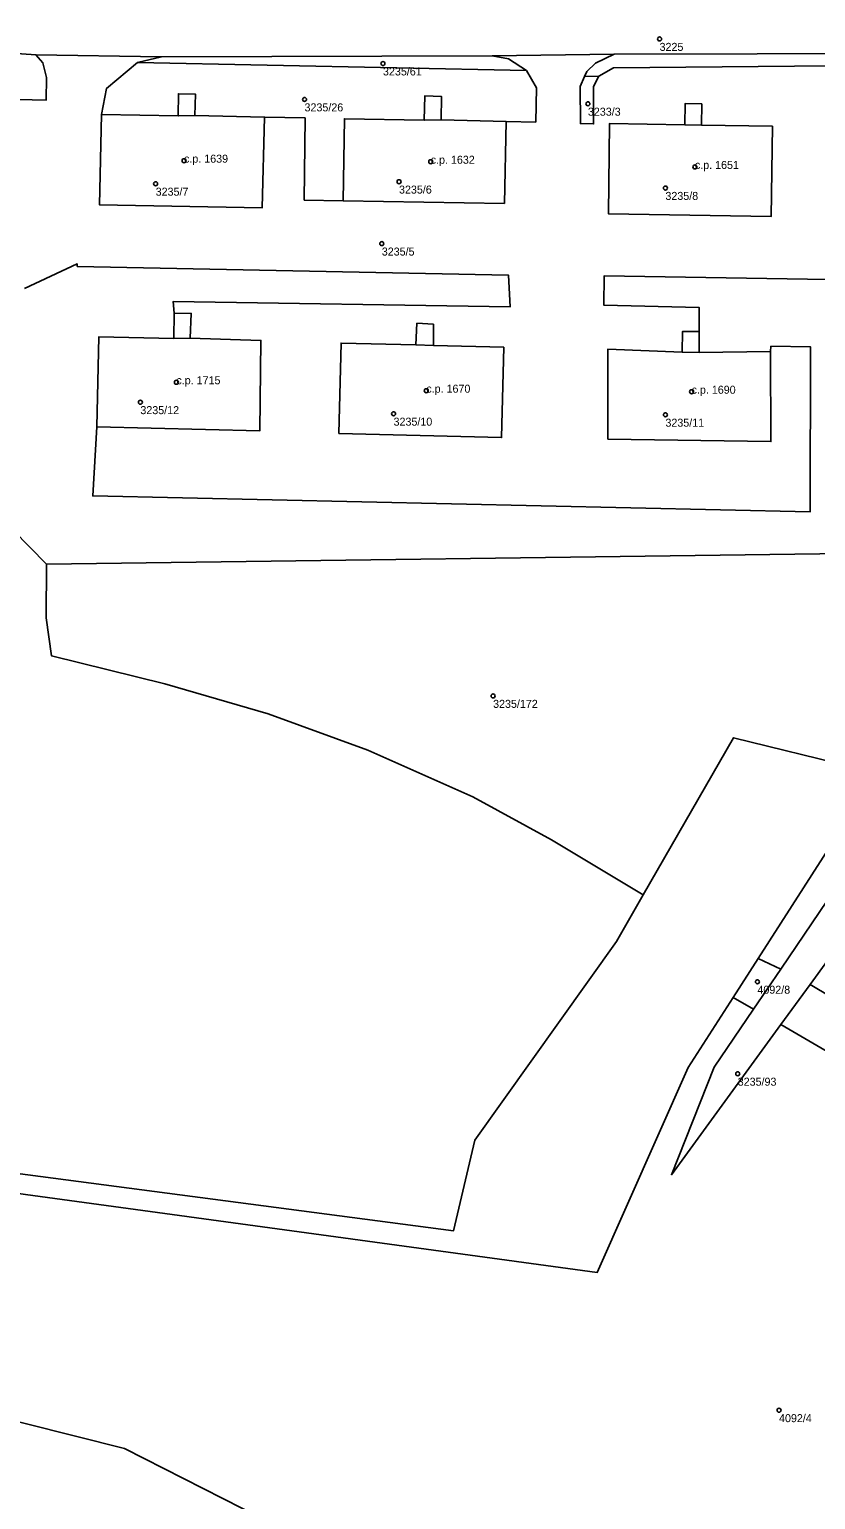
# Model space of a CAD drawing. Extents: x -878211 to -870363, y -1058464 to -1052522.
# Drawn here: x -875238.5 to -875140.3, y -1056719.1 to -1056535.5 of the extents above; entities that cross this region are included whole.
import ezdxf

# ---------------------------------------------------------------- set-up
doc = ezdxf.new("R2010")
doc.units = 0
for name, color, linetype in [('Definiční body', 7, 'Continuous'), ('Polygon budovy', 7, 'Continuous'), ('Polygon parcely', 7, 'Continuous')]:
    doc.layers.add(name, color=color, linetype=linetype)

msp = doc.modelspace()

# ---------------------------------------------------------------- linework, layer by layer
at = {"layer": 'Definiční body'}
for centre in [(-875159.76, -1056536.67994), (-875194.3, -1056539.74994), (-875204.1, -1056544.23994), (-875168.71, -1056544.77994), (-875219.15, -1056551.88994), (-875188.34, -1056552.01994), (-875155.35, -1056552.66994), (-875222.69, -1056554.76994), (-875192.3, -1056554.50994), (-875159.03, -1056555.29994), (-875194.45, -1056562.24994), (-875220.1, -1056579.56994), (-875188.89, -1056580.61994), (-875155.76, -1056580.74994), (-875224.6, -1056582.05994), (-875192.98, -1056583.49994), (-875159.03, -1056583.62994), (-875180.55, -1056618.74994), (-875147.54, -1056654.45994), (-875150, -1056665.94994), (-875144.84, -1056707.97994)]:
    msp.add_circle(centre, 0.25, dxfattribs=at)
at = {"layer": 'Polygon budovy'}
for points in [[(-875229.71, -1056557.4), (-875209.38, -1056557.77), (-875209.08, -1056546.45), (-875217.8, -1056546.25), (-875219.87, -1056546.29), (-875229.46, -1056546.1)], [(-875199.29, -1056556.89), (-875179.13, -1056557.23), (-875178.92, -1056547.01), (-875187.05, -1056546.8), (-875189.15, -1056546.84), (-875199.12, -1056546.64)], [(-875166.13, -1056558.53), (-875145.81, -1056558.85), (-875145.66, -1056547.59), (-875154.52, -1056547.46), (-875156.61, -1056547.41), (-875166.01, -1056547.23)], [(-875230.02, -1056585.15), (-875209.67, -1056585.62), (-875209.55, -1056574.33), (-875218.37, -1056574.06), (-875220.43, -1056574.1), (-875229.78, -1056573.88)], [(-875199.81, -1056585.98), (-875179.5, -1056586.48), (-875179.22, -1056575.2), (-875188, -1056574.97), (-875190.19, -1056574.91), (-875199.54, -1056574.67)], [(-875166.23, -1056575.45), (-875166.22, -1056586.67), (-875145.85, -1056586.97), (-875145.89, -1056575.71), (-875154.82, -1056575.84), (-875156.93, -1056575.8)]]:
    msp.add_lwpolyline(points, close=True, dxfattribs=at)
at = {"layer": 'Polygon parcely'}
for points in [[(-875140.1, -1056532.21), (-875152.33, -1056530.58), (-875152.44, -1056532.68), (-875153.43, -1056532.87), (-875155.48, -1056532.95), (-875259.02, -1056533.3), (-875259.1, -1056534.73), (-875259.22, -1056537.17), (-875237.65, -1056538.66), (-875221.97, -1056538.9), (-875180.65, -1056538.78), (-875165.42, -1056538.58), (-875111.86, -1056538.46)], [(-875111.27, -1056539.8), (-875165.51, -1056540.27), (-875167.33, -1056541.35), (-875168, -1056542.6), (-875168.01, -1056547.3), (-875169.65, -1056547.25), (-875169.69, -1056542.63), (-875169.13, -1056541.36), (-875168.86, -1056540.75), (-875167.78, -1056539.72), (-875165.42, -1056538.58), (-875180.65, -1056538.78), (-875178.61, -1056539.17), (-875176.39, -1056540.63), (-875175.12, -1056542.78), (-875175.23, -1056547.06), (-875178.92, -1056547.01), (-875179.13, -1056557.23), (-875199.29, -1056556.89), (-875204.14, -1056556.8), (-875204.02, -1056546.54), (-875209.08, -1056546.45), (-875209.38, -1056557.77), (-875229.71, -1056557.4), (-875229.46, -1056546.1), (-875228.81, -1056542.85), (-875224.94, -1056539.61), (-875221.97, -1056538.9), (-875237.65, -1056538.66), (-875236.79, -1056539.65), (-875236.32, -1056541.49), (-875236.37, -1056544.34), (-875271.64, -1056543.49)], [(-875239.05, -1056567.84), (-875232.48, -1056564.79), (-875232.48, -1056565.09), (-875178.64, -1056566.17), (-875178.41, -1056570.14), (-875220.52, -1056569.48), (-875220.37, -1056570.92), (-875218.24, -1056570.97), (-875218.37, -1056574.06), (-875209.55, -1056574.33), (-875209.67, -1056585.62), (-875230.02, -1056585.15), (-875230.55, -1056593.76), (-875140.94, -1056595.75), (-875140.9, -1056575.15), (-875145.86, -1056575.06), (-875145.89, -1056575.71), (-875145.85, -1056586.97), (-875166.22, -1056586.67), (-875166.23, -1056575.45), (-875156.93, -1056575.8), (-875156.88, -1056573.22), (-875154.82, -1056573.23), (-875154.82, -1056570.21), (-875166.73, -1056569.93), (-875166.67, -1056566.26), (-875136.19, -1056566.77)], [(-875136.19, -1056566.77), (-875166.67, -1056566.26), (-875166.73, -1056569.93), (-875154.82, -1056570.21), (-875154.82, -1056573.23), (-875154.82, -1056575.84), (-875145.89, -1056575.71), (-875145.86, -1056575.06), (-875140.9, -1056575.15), (-875140.94, -1056595.75), (-875230.55, -1056593.76), (-875230.02, -1056585.15), (-875229.78, -1056573.88), (-875220.43, -1056574.1), (-875220.37, -1056570.92), (-875220.52, -1056569.48), (-875178.41, -1056570.14), (-875178.64, -1056566.17), (-875232.48, -1056565.09), (-875232.48, -1056564.79), (-875239.05, -1056567.84)], [(-875248.8, -1056589.58), (-875236.32, -1056602.29), (-875136.63, -1056600.96)], [(-875135.57, -1056627.63), (-875150.54, -1056623.98), (-875161.79, -1056643.58), (-875165.14, -1056649.42), (-875182.81, -1056674.24), (-875185.5, -1056685.58), (-875249.77, -1056677.11), (-875312.58, -1056672.35), (-875348.63, -1056671.78), (-875416.46, -1056673.09), (-875404.82, -1056653.65), (-875399.48, -1056610.9), (-875402.56, -1056593.86), (-875403.99, -1056596.85), (-875412.09, -1056596.61)], [(-875418.33, -1056675.87), (-875403.05, -1056675.7), (-875324.65, -1056674.8), (-875249.34, -1056679.6), (-875167.54, -1056690.76), (-875156.2, -1056665.18), (-875150.59, -1056656.44), (-875147.44, -1056651.53), (-875135.09, -1056632.27)], [(-875131.33, -1056667.53), (-875144.62, -1056659.79), (-875158.29, -1056678.56), (-875152.95, -1056665.14), (-875148.03, -1056657.88), (-875150.59, -1056656.44), (-875156.2, -1056665.18), (-875167.54, -1056690.76), (-875249.34, -1056679.6), (-875324.65, -1056674.8), (-875403.05, -1056675.7), (-875332.16, -1056686.21), (-875226.57, -1056712.76), (-875120.98, -1056766.48)], [(-875416.4, -1056713.01), (-875408.11, -1056714.61), (-875345.75, -1056722.02), (-875240.16, -1056749.19), (-875146.3, -1056797.97), (-875134.32, -1056809.28), (-875117.35, -1056820.06), (-875115.93, -1056815.48), (-875112.75, -1056808.22), (-875113.37, -1056814.13), (-875102.75, -1056787.02), (-875109.25, -1056779.69), (-875120.98, -1056766.48), (-875226.57, -1056712.76), (-875332.16, -1056686.21), (-875403.05, -1056675.7), (-875418.33, -1056675.87)]]:
    msp.add_lwpolyline(points, dxfattribs=at)
for points in [[(-875259.22, -1056537.17), (-875259.1, -1056534.73), (-875261.72, -1056535.04), (-875266.97, -1056533.79), (-875267.96, -1056540.29), (-875281.72, -1056541.28), (-875296.54, -1056543.51), (-875313.42, -1056546.47), (-875315.41, -1056546.95), (-875303.53, -1056568.52), (-875300.73, -1056568.5), (-875300.61, -1056561.1), (-875300.43, -1056549.82), (-875291.04, -1056550.02), (-875290.97, -1056547.29), (-875290.97, -1056544.03), (-875271.64, -1056543.49), (-875236.37, -1056544.34), (-875236.32, -1056541.49), (-875236.79, -1056539.65), (-875237.65, -1056538.66)], [(-875167.78, -1056539.72), (-875168.86, -1056540.75), (-875169.13, -1056541.36), (-875167.33, -1056541.35), (-875165.51, -1056540.27), (-875111.27, -1056539.8), (-875111.86, -1056538.46), (-875165.42, -1056538.58)], [(-875176.39, -1056540.63), (-875224.94, -1056539.61), (-875228.81, -1056542.85), (-875229.46, -1056546.1), (-875219.87, -1056546.29), (-875219.85, -1056543.53), (-875217.73, -1056543.56), (-875217.8, -1056546.25), (-875209.08, -1056546.45), (-875204.02, -1056546.54), (-875204.14, -1056556.8), (-875199.29, -1056556.89), (-875199.12, -1056546.64), (-875189.15, -1056546.84), (-875189.08, -1056543.79), (-875187, -1056543.85), (-875187.05, -1056546.8), (-875178.92, -1056547.01), (-875175.23, -1056547.06), (-875175.12, -1056542.78)], [(-875176.39, -1056540.63), (-875178.61, -1056539.17), (-875180.65, -1056538.78), (-875221.97, -1056538.9), (-875224.94, -1056539.61)], [(-875168, -1056542.6), (-875167.33, -1056541.35), (-875169.13, -1056541.36), (-875169.69, -1056542.63), (-875169.65, -1056547.25), (-875168.01, -1056547.3)], [(-875229.46, -1056546.1), (-875229.71, -1056557.4), (-875209.38, -1056557.77), (-875209.08, -1056546.45), (-875217.8, -1056546.25), (-875217.73, -1056543.56), (-875219.85, -1056543.53), (-875219.87, -1056546.29)], [(-875189.15, -1056546.84), (-875199.12, -1056546.64), (-875199.29, -1056556.89), (-875179.13, -1056557.23), (-875178.92, -1056547.01), (-875187.05, -1056546.8), (-875187, -1056543.85), (-875189.08, -1056543.79)], [(-875154.48, -1056544.78), (-875156.56, -1056544.74), (-875156.61, -1056547.41), (-875166.01, -1056547.23), (-875166.13, -1056558.53), (-875145.81, -1056558.85), (-875145.66, -1056547.59), (-875154.52, -1056547.46)], [(-875154.48, -1056544.78), (-875154.52, -1056547.46), (-875145.66, -1056547.59), (-875145.81, -1056558.85), (-875166.13, -1056558.53), (-875166.01, -1056547.23), (-875156.61, -1056547.41), (-875156.56, -1056544.74)], [(-875230.02, -1056585.15), (-875209.67, -1056585.62), (-875209.55, -1056574.33), (-875218.37, -1056574.06), (-875218.24, -1056570.97), (-875220.37, -1056570.92), (-875220.43, -1056574.1), (-875229.78, -1056573.88)], [(-875199.81, -1056585.98), (-875179.5, -1056586.48), (-875179.22, -1056575.2), (-875188, -1056574.97), (-875188.01, -1056572.32), (-875190.07, -1056572.19), (-875190.19, -1056574.91), (-875199.54, -1056574.67)], [(-875199.81, -1056585.98), (-875199.54, -1056574.67), (-875190.19, -1056574.91), (-875190.07, -1056572.19), (-875188.01, -1056572.32), (-875188, -1056574.97), (-875179.22, -1056575.2), (-875179.5, -1056586.48)], [(-875154.82, -1056573.23), (-875156.88, -1056573.22), (-875156.93, -1056575.8), (-875166.23, -1056575.45), (-875166.22, -1056586.67), (-875145.85, -1056586.97), (-875145.89, -1056575.71), (-875154.82, -1056575.84)], [(-875235.7, -1056613.74), (-875236.35, -1056608.98), (-875236.32, -1056602.29), (-875248.8, -1056589.58), (-875278.52, -1056581.55), (-875304.34, -1056581.6), (-875351.67, -1056581.91), (-875396.73, -1056582.14), (-875402.56, -1056593.86), (-875399.48, -1056610.9), (-875404.82, -1056653.65), (-875416.46, -1056673.09), (-875348.63, -1056671.78), (-875312.58, -1056672.35), (-875249.77, -1056677.11), (-875185.5, -1056685.58), (-875182.81, -1056674.24), (-875165.14, -1056649.42), (-875161.79, -1056643.58), (-875173.25, -1056636.71), (-875183.08, -1056631.34), (-875196.21, -1056625.52), (-875208.62, -1056621), (-875221.55, -1056617.25)], [(-875136.63, -1056600.96), (-875236.32, -1056602.29), (-875236.35, -1056608.98), (-875235.7, -1056613.74), (-875221.55, -1056617.25), (-875208.62, -1056621), (-875196.21, -1056625.52), (-875183.08, -1056631.34), (-875173.25, -1056636.71), (-875161.79, -1056643.58), (-875150.54, -1056623.98), (-875135.57, -1056627.63), (-875132.43, -1056620.89), (-875134.07, -1056620.89), (-875136.87, -1056620), (-875138.55, -1056617.84)], [(-875147.44, -1056651.53), (-875144.63, -1056652.87), (-875132.07, -1056634.34), (-875135.09, -1056632.27)], [(-875158.29, -1056678.56), (-875144.62, -1056659.79), (-875140.97, -1056654.78), (-875129.58, -1056639.14), (-875132.07, -1056634.34), (-875144.63, -1056652.87), (-875148.03, -1056657.88), (-875152.95, -1056665.14)], [(-875090.61, -1056684.77), (-875086.74, -1056667.79), (-875109.41, -1056653.11), (-875111.51, -1056651.71), (-875128.02, -1056640.29), (-875129.58, -1056639.14), (-875140.97, -1056654.78), (-875106.91, -1056675.12), (-875097.17, -1056680.82)], [(-875147.44, -1056651.53), (-875150.59, -1056656.44), (-875148.03, -1056657.88), (-875144.63, -1056652.87)], [(-875090.61, -1056684.77), (-875097.17, -1056680.82), (-875106.91, -1056675.12), (-875140.97, -1056654.78), (-875144.62, -1056659.79), (-875131.33, -1056667.53), (-875115.91, -1056677.03), (-875107.77, -1056682.42), (-875104.09, -1056685.1), (-875095.8, -1056690.63), (-875091.91, -1056693.44), (-875091.43, -1056688.36)]]:
    msp.add_lwpolyline(points, close=True, dxfattribs=at)

# ---------------------------------------------------------------- texts
at = {"layer": 'Definiční body'}
for s, p in [('3225', (-875159.76, -1056538.169)), ('3235/61', (-875194.3, -1056541.239)), ('3235/26', (-875204.1, -1056545.729)), ('3233/3', (-875168.71, -1056546.269)), ('c.p. 1639', (-875219.15, -1056552.139)), ('c.p. 1632', (-875188.34, -1056552.27)), ('c.p. 1651', (-875155.35, -1056552.919)), ('3235/6', (-875192.3, -1056555.999)), ('3235/7', (-875222.69, -1056556.259)), ('3235/8', (-875159.03, -1056556.789)), ('3235/5', (-875194.45, -1056563.739)), ('c.p. 1715', (-875220.1, -1056579.82)), ('c.p. 1670', (-875188.89, -1056580.87)), ('c.p. 1690', (-875155.76, -1056581)), ('3235/12', (-875224.6, -1056583.549)), ('3235/10', (-875192.98, -1056584.989)), ('3235/11', (-875159.03, -1056585.119)), ('3235/172', (-875180.55, -1056620.239)), ('4092/8', (-875147.54, -1056655.949)), ('3235/93', (-875150, -1056667.439)), ('4092/4', (-875144.84, -1056709.469))]:
    msp.add_text(s, height=0.999996, dxfattribs=at).set_placement(p)

doc.saveas('drawing.dxf')
